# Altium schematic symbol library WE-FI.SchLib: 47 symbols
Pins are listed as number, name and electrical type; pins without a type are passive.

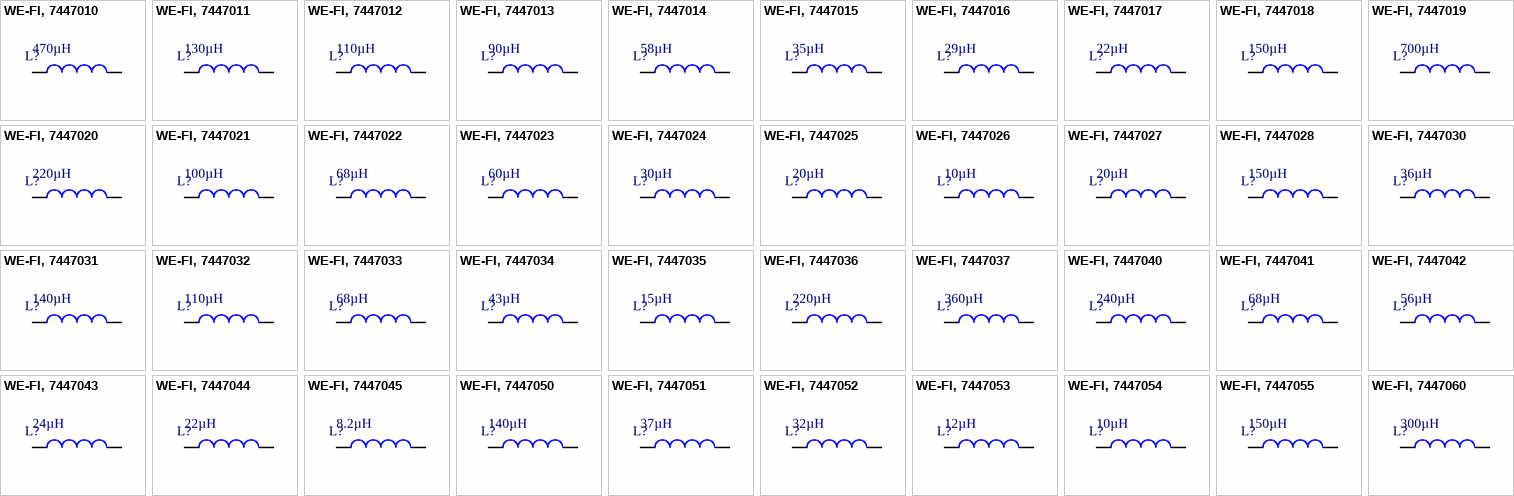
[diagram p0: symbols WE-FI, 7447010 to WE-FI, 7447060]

## WE-FI, 7447010
designator L?  value 470µH
WE-FI Leaded Toroidal Line Choke, L = 470µH; partNo: 7447010; Manufacturer: Wurth Elektronik
footprint 7447010
pins: 1, 2

## WE-FI, 7447011
designator L?  value 130µH
WE-FI Leaded Toroidal Line Choke, L = 130µH; partNo: 7447011; Manufacturer: Wurth Elektronik
footprint 7447011
pins: 1, 2

## WE-FI, 7447012
designator L?  value 110µH
WE-FI Leaded Toroidal Line Choke, L = 110µH; partNo: 7447012; Manufacturer: Wurth Elektronik
footprint 7447012
pins: 1, 2

## WE-FI, 7447013
designator L?  value 90µH
WE-FI Leaded Toroidal Line Choke, L = 90µH; partNo: 7447013; Manufacturer: Wurth Elektronik
footprint 7447013
pins: 1, 2

## WE-FI, 7447014
designator L?  value 58µH
WE-FI Leaded Toroidal Line Choke, L = 58µH; partNo: 7447014; Manufacturer: Wurth Elektronik
footprint 7447014
pins: 1, 2

## WE-FI, 7447015
designator L?  value 35µH
WE-FI Leaded Toroidal Line Choke, L = 35µH; partNo: 7447015; Manufacturer: Wurth Elektronik
footprint 7447015
pins: 1, 2

## WE-FI, 7447016
designator L?  value 29µH
WE-FI Leaded Toroidal Line Choke, L = 29µH; partNo: 7447016; Manufacturer: Wurth Elektronik
footprint 7447016
pins: 1, 2

## WE-FI, 7447017
designator L?  value 22µH
WE-FI Leaded Toroidal Line Choke, L = 22µH; partNo: 7447017; Manufacturer: Wurth Elektronik
footprint 7447017
pins: 1, 2

## WE-FI, 7447018
designator L?  value 150µH
WE-FI Leaded Toroidal Line Choke, L = 150µH; partNo: 7447018; Manufacturer: Wurth Elektronik
footprint 7447018
pins: 1, 2

## WE-FI, 7447019
designator L?  value 700µH
WE-FI Leaded Toroidal Line Choke, L = 700µH; partNo: 7447019; Manufacturer: Wurth Elektronik
footprint 7447019
pins: 1, 2

## WE-FI, 7447020
designator L?  value 220µH
WE-FI Leaded Toroidal Line Choke, L = 220µH; partNo: 7447020; Manufacturer: Wurth Elektronik
footprint 7447020
pins: 1, 2

## WE-FI, 7447021
designator L?  value 100µH
WE-FI Leaded Toroidal Line Choke, L = 100µH; partNo: 7447021; Manufacturer: Wurth Elektronik
footprint 7447021
pins: 1, 2

## WE-FI, 7447022
designator L?  value 68µH
WE-FI Leaded Toroidal Line Choke, L = 68µH; partNo: 7447022; Manufacturer: Wurth Elektronik
footprint 7447022
pins: 1, 2

## WE-FI, 7447023
designator L?  value 60µH
WE-FI Leaded Toroidal Line Choke, L = 60µH; partNo: 7447023; Manufacturer: Wurth Elektronik
footprint 7447023
pins: 1, 2

## WE-FI, 7447024
designator L?  value 30µH
WE-FI Leaded Toroidal Line Choke, L = 30µH; partNo: 7447024; Manufacturer: Wurth Elektronik
footprint 7447024
pins: 1, 2

## WE-FI, 7447025
designator L?  value 20µH
WE-FI Leaded Toroidal Line Choke, L = 20µH; partNo: 7447025; Manufacturer: Wurth Elektronik
footprint 7447025
pins: 1, 2

## WE-FI, 7447026
designator L?  value 10µH
WE-FI Leaded Toroidal Line Choke, L = 10µH; partNo: 7447026; Manufacturer: Wurth Elektronik
footprint 7447026
pins: 1, 2

## WE-FI, 7447027
designator L?  value 20µH
WE-FI Leaded Toroidal Line Choke, L = 20µH; partNo: 7447027; Manufacturer: Wurth Elektronik
footprint 7447027
pins: 1, 2

## WE-FI, 7447028
designator L?  value 150µH
WE-FI Leaded Toroidal Line Choke, L = 150µH; partNo: 7447028; Manufacturer: Wurth Elektronik
footprint 7447028
pins: 1, 2

## WE-FI, 7447030
designator L?  value 36µH
WE-FI Leaded Toroidal Line Choke, L = 36µH; partNo: 7447030; Manufacturer: Wurth Elektronik
footprint 7447030
pins: 1, 2

## WE-FI, 7447031
designator L?  value 140µH
WE-FI Leaded Toroidal Line Choke, L = 140µH; partNo: 7447031; Manufacturer: Wurth Elektronik
footprint 7447031
pins: 1, 2

## WE-FI, 7447032
designator L?  value 110µH
WE-FI Leaded Toroidal Line Choke, L = 110µH; partNo: 7447032; Manufacturer: Wurth Elektronik
footprint 7447032
pins: 1, 2

## WE-FI, 7447033
designator L?  value 68µH
WE-FI Leaded Toroidal Line Choke, L = 68µH; partNo: 7447033; Manufacturer: Wurth Elektronik
footprint 7447033
pins: 1, 2

## WE-FI, 7447034
designator L?  value 43µH
WE-FI Leaded Toroidal Line Choke, L = 43µH; partNo: 7447034; Manufacturer: Wurth Elektronik
footprint 7447034
pins: 1, 2

## WE-FI, 7447035
designator L?  value 15µH
WE-FI Leaded Toroidal Line Choke, L = 15µH; partNo: 7447035; Manufacturer: Wurth Elektronik
footprint 7447035
pins: 1, 2

## WE-FI, 7447036
designator L?  value 220µH
WE-FI Leaded Toroidal Line Choke, L = 220µH; partNo: 7447036; Manufacturer: Wurth Elektronik
footprint 7447036
pins: 1, 2

## WE-FI, 7447037
designator L?  value 360µH
WE-FI Leaded Toroidal Line Choke, L = 360µH; partNo: 7447037; Manufacturer: Wurth Elektronik
footprint 7447037
pins: 1, 2

## WE-FI, 7447040
designator L?  value 240µH
WE-FI Leaded Toroidal Line Choke, L = 240µH; partNo: 7447040; Manufacturer: Wurth Elektronik
footprint 7447040
pins: 1, 2

## WE-FI, 7447041
designator L?  value 68µH
WE-FI Leaded Toroidal Line Choke, L = 68µH; partNo: 7447041; Manufacturer: Wurth Elektronik
footprint 7447041
pins: 1, 2

## WE-FI, 7447042
designator L?  value 56µH
WE-FI Leaded Toroidal Line Choke, L = 56µH; partNo: 7447042; Manufacturer: Wurth Elektronik
footprint 7447042
pins: 1, 2

## WE-FI, 7447043
designator L?  value 24µH
WE-FI Leaded Toroidal Line Choke, L = 24µH; partNo: 7447043; Manufacturer: Wurth Elektronik
footprint 7447043
pins: 1, 2

## WE-FI, 7447044
designator L?  value 22µH
WE-FI Leaded Toroidal Line Choke, L = 22µH; partNo: 7447044; Manufacturer: Wurth Elektronik
footprint 7447044
pins: 1, 2

## WE-FI, 7447045
designator L?  value 8.2µH
WE-FI Leaded Toroidal Line Choke, L = 8.2µH; partNo: 7447045; Manufacturer: Wurth Elektronik
footprint 7447045
pins: 1, 2

## WE-FI, 7447050
designator L?  value 140µH
WE-FI Leaded Toroidal Line Choke, L = 140µH; partNo: 7447050; Manufacturer: Wurth Elektronik
footprint 7447050
pins: 1, 2

## WE-FI, 7447051
designator L?  value 37µH
WE-FI Leaded Toroidal Line Choke, L = 37µH; partNo: 7447051; Manufacturer: Wurth Elektronik
footprint 7447051
pins: 1, 2

## WE-FI, 7447052
designator L?  value 32µH
WE-FI Leaded Toroidal Line Choke, L = 32µH; partNo: 7447052; Manufacturer: Wurth Elektronik
footprint 7447052
pins: 1, 2

## WE-FI, 7447053
designator L?  value 12µH
WE-FI Leaded Toroidal Line Choke, L = 12µH; partNo: 7447053; Manufacturer: Wurth Elektronik
footprint 7447053
pins: 1, 2

## WE-FI, 7447054
designator L?  value 10µH
WE-FI Leaded Toroidal Line Choke, L = 10µH; partNo: 7447054; Manufacturer: Wurth Elektronik
footprint 7447054
pins: 1, 2

## WE-FI, 7447055
designator L?  value 150µH
WE-FI Leaded Toroidal Line Choke, L = 150µH; partNo: 7447055; Manufacturer: Wurth Elektronik
footprint 7447055
pins: 1, 2

## WE-FI, 7447060
designator L?  value 300µH
WE-FI Leaded Toroidal Line Choke, L = 300µH; partNo: 7447060; Manufacturer: Wurth Elektronik
footprint 7447060
pins: 1, 2

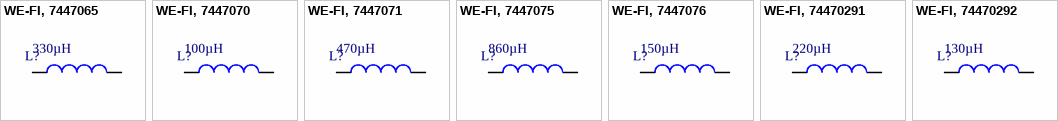
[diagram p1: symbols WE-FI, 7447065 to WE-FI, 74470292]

## WE-FI, 7447065
designator L?  value 330µH
WE-FI Leaded Toroidal Line Choke, L = 330µH; partNo: 7447065; Manufacturer: Wurth Elektronik
footprint 7447065
pins: 1, 2

## WE-FI, 7447070
designator L?  value 100µH
WE-FI Leaded Toroidal Line Choke, L = 100µH; partNo: 7447070; Manufacturer: Wurth Elektronik
footprint 7447070
pins: 1, 2

## WE-FI, 7447071
designator L?  value 470µH
WE-FI Leaded Toroidal Line Choke, L = 470µH; partNo: 7447071; Manufacturer: Wurth Elektronik
footprint 7447071
pins: 1, 2

## WE-FI, 7447075
designator L?  value 860µH
WE-FI Leaded Toroidal Line Choke, L = 860µH; partNo: 7447075; Manufacturer: Wurth Elektronik
footprint 7447075
pins: 1, 2

## WE-FI, 7447076
designator L?  value 150µH
WE-FI Leaded Toroidal Line Choke, L = 150µH; partNo: 7447076; Manufacturer: Wurth Elektronik
footprint 7447076
pins: 1, 2

## WE-FI, 74470291
designator L?  value 220µH
WE-FI Leaded Toroidal Line Choke, L = 220µH; partNo: 74470291; Manufacturer: Wurth Elektronik
footprint 74470291
pins: 1, 2

## WE-FI, 74470292
designator L?  value 130µH
WE-FI Leaded Toroidal Line Choke, L = 130µH; partNo: 74470292; Manufacturer: Wurth Elektronik
footprint 74470292
pins: 1, 2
